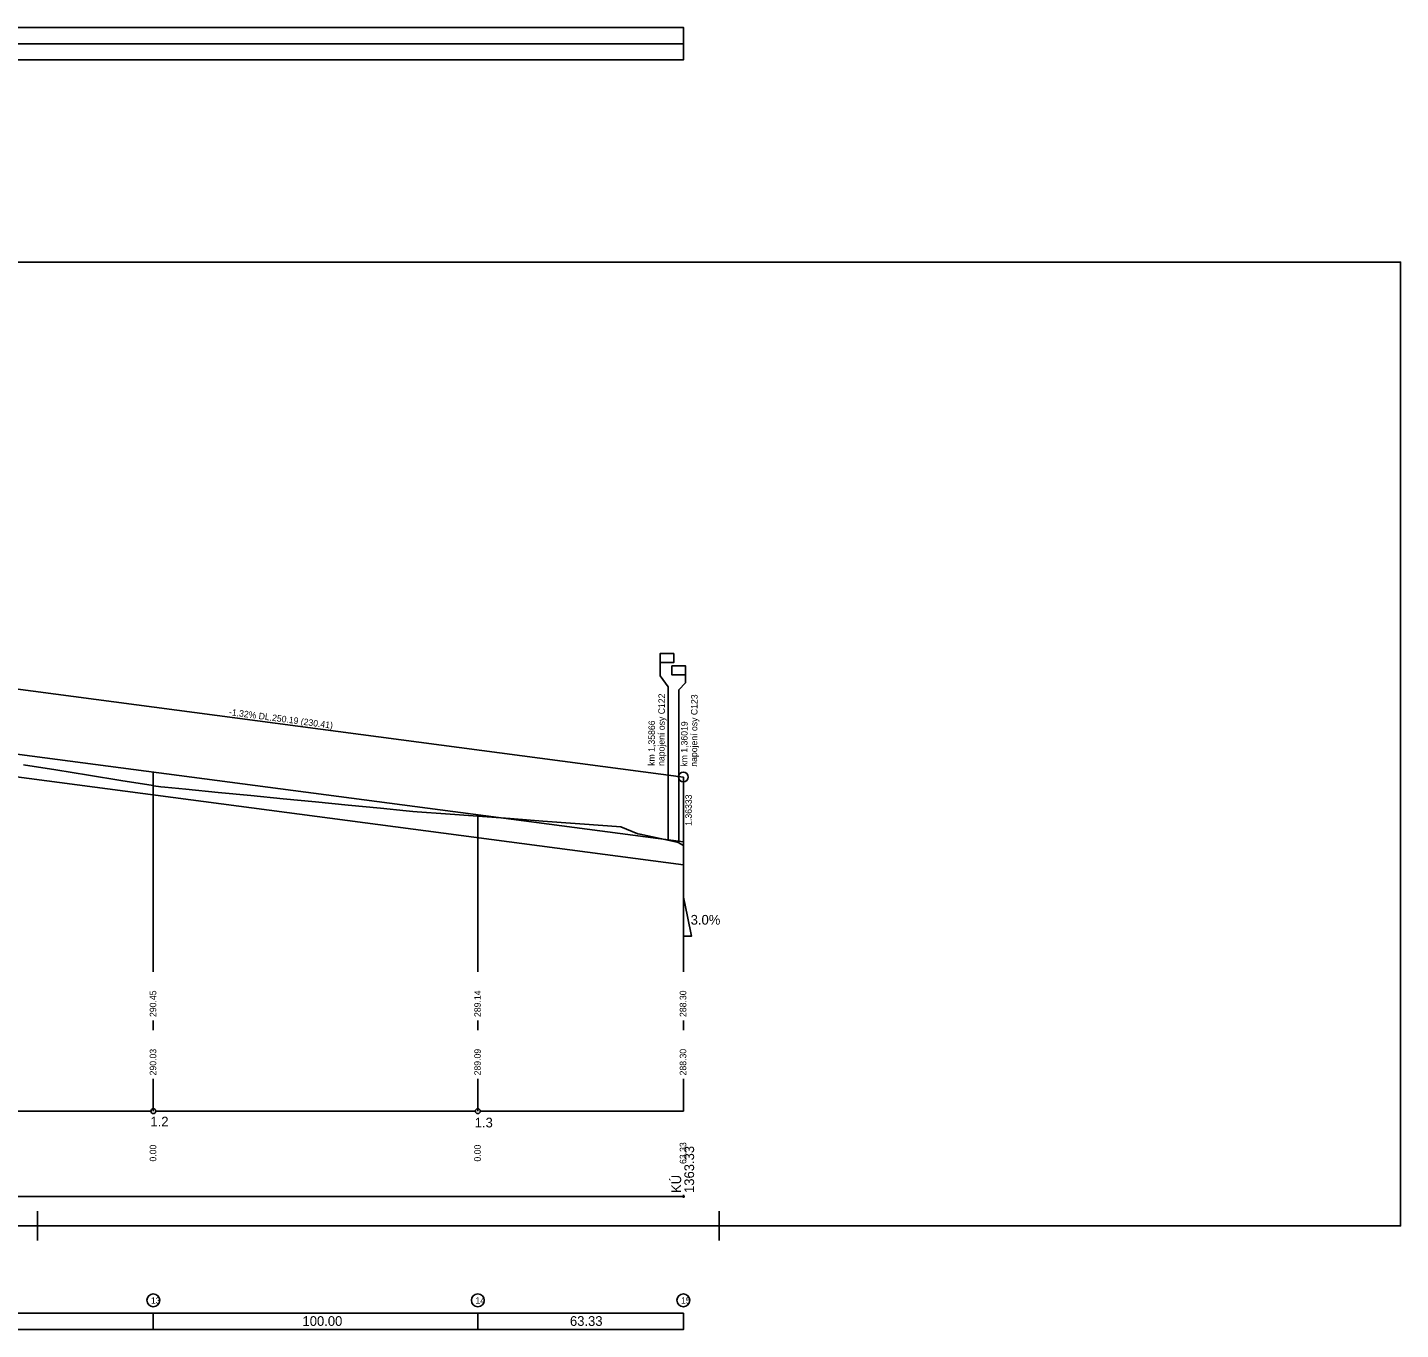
# Model space of a CAD drawing. Extents: x 1677 to 1845, y 131 to 171.
# Drawn here: x 1802.21 to 1844.52, y 130.76 to 170.89 of the extents above; entities that cross this region are included whole.
import ezdxf

# ---------------------------------------------------------------- set-up
doc = ezdxf.new("R2010")
doc.units = 0
for name, color, linetype in [('_prikopy', 7, 'Continuous'), ('NOVY_STAV', 7, 'Continuous'), ('REZY_PO', 7, 'Continuous'), ('SESTAVY_REZU_PO', 7, 'Continuous'), ('SKLONOVE_POMERY', 7, 'Continuous'), ('SMEROVE_POMERY', 7, 'Continuous'), ('SMEROVE_POMERY_KOD', 7, 'Continuous'), ('SVK_STAT', 7, 'Continuous'), ('TABULKY', 7, 'Continuous'), ('u_pricne_rezy', 7, 'Continuous'), ('x_formát_rám', 7, 'Continuous')]:
    doc.layers.add(name, color=color, linetype=linetype)

msp = doc.modelspace()

# ---------------------------------------------------------------- linework, layer by layer
at = {"layer": '_prikopy'}
msp.add_lwpolyline([(1799.291, 148.131), (1822.422, 145.081)], dxfattribs=at)
at = {"layer": 'NOVY_STAV'}
for p, q in [((1821.959, 145.848), (1821.959, 150.57)), ((1822.279, 145.806), (1822.279, 150.472))]:
    msp.add_line(p, q, dxfattribs=at)
for points in [[(1822.127, 151.594), (1821.707, 151.594), (1821.707, 151.314), (1822.127, 151.314)], [(1822.064, 151.218), (1822.484, 151.218), (1822.484, 150.938), (1822.064, 150.938)]]:
    msp.add_lwpolyline(points, close=True, dxfattribs=at)
for points in [[(1821.707, 151.594), (1821.707, 150.909), (1821.959, 150.57)], [(1797.404, 151.086), (1822.422, 147.787)], [(1822.484, 151.218), (1822.484, 150.687), (1822.279, 150.472)], [(1799.381, 148.825), (1822.422, 145.787)], [(1822.422, 145.787), (1822.422, 147.787)]]:
    msp.add_lwpolyline(points, dxfattribs=at)
msp.add_circle((1822.422, 147.787), 0.15, dxfattribs=at)
at = {"layer": 'REZY_PO'}
msp.add_lwpolyline([(1802.089, 148.167), (1803.089, 148.005), (1804.089, 147.843), (1805.089, 147.682), (1806.08, 147.521), (1806.089, 147.52), (1806.251, 147.492), (1806.322, 147.481), (1806.442, 147.473), (1807.089, 147.41), (1808.089, 147.312), (1809.089, 147.214), (1810.089, 147.116), (1811.089, 147.019), (1812.089, 146.921), (1813.089, 146.823), (1813.88, 146.746), (1814.089, 146.729), (1814.221, 146.718), (1815.089, 146.654), (1816.089, 146.579), (1816.089, 146.579), (1817.089, 146.504), (1818.089, 146.429), (1819.089, 146.355), (1820.089, 146.28), (1820.491, 146.25), (1821.021, 146.041), (1821.089, 146.026), (1822.089, 145.806), (1822.267, 145.767), (1822.422, 145.677)], dxfattribs=at)
at = {"layer": 'SESTAVY_REZU_PO'}
for points in [[(1796.164, 137.487), (1806.014, 137.487)], [(1806.164, 137.487), (1816.014, 137.487)], [(1816.164, 137.487), (1822.422, 137.487)]]:
    msp.add_lwpolyline(points, dxfattribs=at)
for centre in [(1806.089, 137.487), (1816.089, 137.487)]:
    msp.add_circle(centre, 0.075, dxfattribs=at)
at = {"layer": 'SKLONOVE_POMERY'}
msp.add_lwpolyline([(1822.422, 142.887), (1822.422, 144.087), (1822.422, 144.087), (1822.548, 143.487), (1822.674, 142.887), (1822.422, 142.887)], dxfattribs=at)
at = {"layer": 'SMEROVE_POMERY'}
msp.add_lwpolyline([(1686.089, 134.864), (1729.605, 134.864), (1729.605, 135.364), (1738.976, 135.364), (1738.976, 134.864), (1822.422, 134.864)], dxfattribs=at)
at = {"layer": 'SMEROVE_POMERY_KOD'}
for points in [[(1822.372, 134.864), (1822.472, 134.864)], [(1822.422, 134.814), (1822.422, 134.914)]]:
    msp.add_lwpolyline(points, dxfattribs=at)
at = {"layer": 'SVK_STAT'}
for points in [[(1806.089, 141.787), (1806.089, 147.941)], [(1816.089, 141.787), (1816.089, 146.622)], [(1822.422, 141.787), (1822.422, 145.787)], [(1806.089, 139.987), (1806.089, 140.287)], [(1816.089, 139.987), (1816.089, 140.287)], [(1822.422, 139.987), (1822.422, 140.287)], [(1806.089, 137.487), (1806.089, 138.487)], [(1816.089, 137.487), (1816.089, 138.487)], [(1822.422, 137.487), (1822.422, 138.487)]]:
    msp.add_lwpolyline(points, dxfattribs=at)
at = {"layer": 'TABULKY'}
for points in [[(1686.089, 169.889), (1822.422, 169.889), (1822.422, 170.889), (1686.089, 170.889), (1686.089, 169.889)], [(1686.089, 170.389), (1822.422, 170.389)]]:
    msp.add_lwpolyline(points, dxfattribs=at)
at = {"layer": 'u_pricne_rezy'}
for points in [[(1686.089, 130.759), (1822.422, 130.759), (1822.422, 131.259), (1686.089, 131.259), (1686.089, 130.759)], [(1806.089, 130.759), (1806.089, 131.259)], [(1816.089, 130.759), (1816.089, 131.259)]]:
    msp.add_lwpolyline(points, dxfattribs=at)
for centre in [(1806.089, 131.659), (1816.089, 131.659), (1822.422, 131.659)]:
    msp.add_circle(centre, 0.2, dxfattribs=at)
at = {"layer": 'x_formát_rám'}
for p, q in [((1802.523, 133.505), (1802.523, 134.405)), ((1823.523, 133.505), (1823.523, 134.405))]:
    msp.add_line(p, q, dxfattribs=at)
msp.add_lwpolyline([(1676.523, 133.955), (1844.523, 133.955), (1844.523, 163.655), (1676.523, 163.655)], close=True, dxfattribs=at)

# ---------------------------------------------------------------- texts
at = {"layer": 'NOVY_STAV'}
for s, rotation, p in [('napojení osy C122', 89.5404, (1821.838, 148.129)), ('napojení osy C123', 89.5404, (1822.844, 148.103)), ('-1.32% DL.250.19 (230.41)', 352.4883, (1808.411, 149.697)), ('km 1,35866', 89.5404, (1821.538, 148.132)), ('km 1,36019', 89.5404, (1822.544, 148.105)), (' 1.36333', 90, (1822.683, 146.208))]:
    msp.add_text(s, height=0.2, rotation=rotation, dxfattribs=at).set_placement(p)
at = {"layer": 'SESTAVY_REZU_PO'}
for s, p in [('1.2', (1805.999, 137.018)), ('1.3', (1815.993, 136.988))]:
    msp.add_text(s, height=0.3, dxfattribs=at).set_placement(p)
at = {"layer": 'SKLONOVE_POMERY'}
msp.add_text('3.0%', height=0.3, dxfattribs=at).set_placement((1822.648, 143.237))
at = {"layer": 'SMEROVE_POMERY_KOD'}
for s, p in [('1363.33', (1822.754, 134.967)), ('KÚ', (1822.354, 134.967))]:
    msp.add_text(s, height=0.3, rotation=90, dxfattribs=at).set_placement(p)
at = {"layer": 'SVK_STAT'}
for s, p in [(' 290.45', (1806.179, 140.317)), (' 289.14', (1816.179, 140.317)), (' 288.30', (1822.512, 140.317)), (' 290.03', (1806.179, 138.517)), (' 289.09', (1816.179, 138.517)), (' 288.30', (1822.512, 138.517)), ('  0.00', (1806.179, 135.787)), ('  0.00', (1816.179, 135.787)), (' 63.33', (1822.512, 135.787))]:
    msp.add_text(s, height=0.2, rotation=90, dxfattribs=at).set_placement(p)
at = {"layer": 'u_pricne_rezy'}
for s, height, p in [('13', 0.2, (1806.016, 131.554)), ('14', 0.2, (1816.016, 131.554)), ('15', 0.2, (1822.35, 131.554)), ('100.00', 0.3, (1810.686, 130.871)), ('63.33', 0.3, (1818.928, 130.871))]:
    msp.add_text(s, height=height, dxfattribs=at).set_placement(p)

doc.saveas('drawing.dxf')
